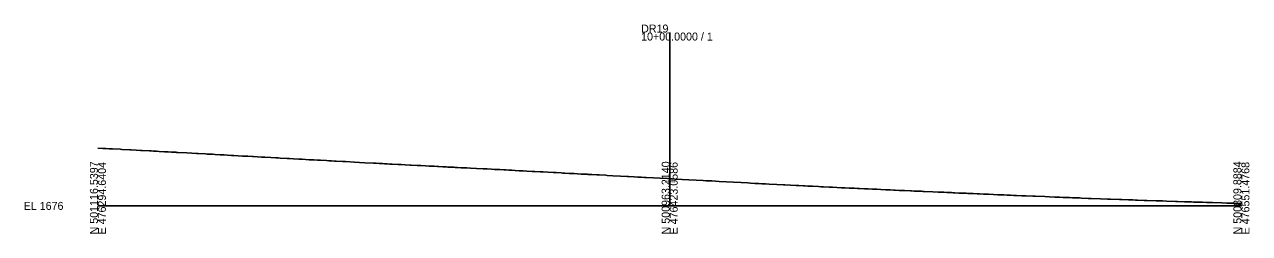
# Model space of a CAD drawing. Extents: x 79370 to 79799, y -95930 to -94349.
# Drawn here: x 79370.3 to 79798.8, y -95930.2 to -95856.9 of the extents above; entities that cross this region are included whole.
import ezdxf

# ---------------------------------------------------------------- set-up
doc = ezdxf.new("R2010")
doc.units = 0
for name, color, linetype in [('Exist Cross Section Cell', 7, 'Continuous'), ('Exist XS Center Line Elevation Label', 7, 'Continuous'), ('Exist XS Ground Line', 7, 'Continuous')]:
    doc.layers.add(name, color=color, linetype=linetype)

msp = doc.modelspace()

# ---------------------------------------------------------------- linework, layer by layer
at = {"layer": 'Exist Cross Section Cell'}
for p, q in [((79596.01, -95920.51), (79596.01, -95859.75)), ((79396.01, -95920.51), (79596.01, -95920.51)), ((79596.01, -95920.51), (79796.01, -95920.51))]:
    msp.add_line(p, q, dxfattribs=at)
at = {"layer": 'Exist XS Ground Line'}
msp.add_lwpolyline([(79396.01, -95900.26), (79397.73, -95900.35), (79398.72, -95900.4), (79399.88, -95900.47), (79400.53, -95900.5), (79401.09, -95900.53), (79403.77, -95900.68), (79404.31, -95900.71), (79407.19, -95900.86), (79407.62, -95900.88), (79409.4, -95900.98), (79410.89, -95901.06), (79411.53, -95901.09), (79414.03, -95901.23), (79414.67, -95901.26), (79415.41, -95901.3), (79416.52, -95901.36), (79417.44, -95901.41), (79419.3, -95901.52), (79420.55, -95901.59), (79421.79, -95901.66), (79423.27, -95901.73), (79423.64, -95901.76), (79423.95, -95901.77), (79427.09, -95901.94), (79428.91, -95902.04), (79430.47, -95902.13), (79431.04, -95902.16), (79433.6, -95902.3), (79434.19, -95902.33), (79434.9, -95902.37), (79436.03, -95902.43), (79436.99, -95902.49), (79438.8, -95902.58), (79440.11, -95902.66), (79441.31, -95902.73), (79442.7, -95902.8), (79443.15, -95902.83), (79443.53, -95902.85), (79446.63, -95903.02), (79448.43, -95903.12), (79450.05, -95903.21), (79450.46, -95903.23), (79453.18, -95903.38), (79453.73, -95903.41), (79454.34, -95903.45), (79456.52, -95903.57), (79458.25, -95903.66), (79459.05, -95903.71), (79459.76, -95903.75), (79462.18, -95903.88), (79462.98, -95903.92), (79464.36, -95904), (79466.34, -95904.11), (79467.42, -95904.17), (79469.91, -95904.31), (79471.51, -95904.39), (79472.87, -95904.46), (79473.81, -95904.52), (79476.01, -95904.63), (79476.81, -95904.68), (79477.71, -95904.73), (79478.74, -95904.79), (79479.33, -95904.82), (79481.64, -95904.94), (79482.08, -95904.97), (79482.61, -95905), (79485.76, -95905.17), (79487.46, -95905.26), (79489.4, -95905.36), (79492.35, -95905.52), (79492.8, -95905.54), (79493.31, -95905.57), (79494.39, -95905.63), (79495.58, -95905.69), (79496.29, -95905.72), (79497.22, -95905.77), (79498.17, -95905.83), (79498.95, -95905.87), (79501.04, -95905.98), (79501.38, -95906), (79502.09, -95906.04), (79503.46, -95906.11), (79505.27, -95906.2), (79505.57, -95906.21), (79507.68, -95906.33), (79508.93, -95906.39), (79510.55, -95906.47), (79511.86, -95906.55), (79512.25, -95906.57), (79512.73, -95906.59), (79513.66, -95906.63), (79514.82, -95906.69), (79515.23, -95906.72), (79516.63, -95906.79), (79517.77, -95906.84), (79518.45, -95906.88), (79519.47, -95906.93), (79520.56, -95906.99), (79520.96, -95907), (79521.76, -95907.04), (79523.02, -95907.11), (79524.54, -95907.18), (79525.08, -95907.21), (79526.28, -95907.27), (79528.4, -95907.38), (79530.74, -95907.5), (79531.44, -95907.54), (79531.76, -95907.55), (79532.17, -95907.57), (79533.67, -95907.65), (79534.77, -95907.71), (79536.12, -95907.78), (79536.64, -95907.8), (79537.96, -95907.87), (79538.72, -95907.92), (79539.79, -95907.97), (79540.85, -95908.02), (79541.99, -95908.09), (79543.37, -95908.16), (79544.05, -95908.2), (79544.81, -95908.24), (79546.1, -95908.31), (79547.88, -95908.4), (79548.86, -95908.45), (79550.69, -95908.55), (79551.1, -95908.57), (79551.75, -95908.61), (79553.44, -95908.7), (79555.27, -95908.8), (79556.35, -95908.86), (79558.07, -95908.95), (79558.64, -95908.99), (79559.29, -95909.02), (79560.85, -95909.1), (79561.29, -95909.13), (79562.57, -95909.2), (79563.76, -95909.26), (79565.06, -95909.33), (79566.07, -95909.39), (79567.15, -95909.44), (79567.5, -95909.46), (79568.73, -95909.53), (79570.57, -95909.63), (79571.4, -95909.67), (79573.7, -95909.79), (79574.12, -95909.81), (79576.16, -95909.92), (79578.85, -95910.06), (79581.15, -95910.19), (79581.63, -95910.21), (79583.55, -95910.32), (79584.85, -95910.39), (79585.21, -95910.41), (79586, -95910.45), (79587.26, -95910.52), (79587.75, -95910.55), (79590.3, -95910.68), (79592.68, -95910.81), (79595.22, -95910.95), (79596.01, -95910.99), (79597.77, -95911.09), (79600.36, -95911.22), (79602.68, -95911.35), (79605.3, -95911.49), (79607.67, -95911.61), (79608.8, -95911.67), (79610.16, -95911.75), (79610.78, -95911.78), (79613.37, -95911.92), (79615.84, -95912.06), (79618.36, -95912.2), (79621.05, -95912.34), (79623.36, -95912.47), (79624.23, -95912.51), (79625.84, -95912.6), (79627.25, -95912.67), (79628.27, -95912.73), (79629.52, -95912.79), (79630.86, -95912.86), (79633.52, -95913), (79635.86, -95913.12), (79636.3, -95913.14), (79638.32, -95913.24), (79640.27, -95913.34), (79640.73, -95913.36), (79641.14, -95913.38), (79642.87, -95913.47), (79643.34, -95913.49), (79644.35, -95913.54), (79645.64, -95913.61), (79646, -95913.63), (79648.12, -95913.73), (79649.03, -95913.78), (79649.81, -95913.81), (79651.78, -95913.91), (79652.24, -95913.93), (79652.58, -95913.95), (79652.93, -95913.97), (79654.49, -95914.04), (79656.17, -95914.12), (79657.37, -95914.18), (79658.84, -95914.25), (79659.61, -95914.29), (79660.52, -95914.33), (79661.68, -95914.38), (79662.37, -95914.42), (79664.15, -95914.5), (79664.82, -95914.53), (79665.41, -95914.56), (79666.99, -95914.63), (79668.5, -95914.7), (79669.86, -95914.77), (79671.67, -95914.85), (79672.4, -95914.88), (79673.11, -95914.91), (79674.47, -95914.98), (79674.94, -95915), (79676.3, -95915.06), (79677.45, -95915.11), (79678.21, -95915.15), (79680.21, -95915.23), (79680.65, -95915.25), (79681.49, -95915.29), (79684.12, -95915.4), (79684.59, -95915.43), (79685.01, -95915.44), (79688.08, -95915.58), (79689.93, -95915.67), (79691.6, -95915.73), (79691.92, -95915.75), (79693.01, -95915.81), (79694.6, -95915.87), (79695.14, -95915.89), (79695.8, -95915.92), (79697.12, -95915.99), (79697.85, -95916.02), (79698.68, -95916.05), (79699.68, -95916.1), (79700.34, -95916.13), (79701.11, -95916.16), (79702.22, -95916.21), (79703.56, -95916.27), (79704.35, -95916.3), (79705.76, -95916.36), (79707.57, -95916.44), (79709.31, -95916.52), (79710.81, -95916.58), (79711.33, -95916.6), (79712.87, -95916.67), (79714.05, -95916.71), (79715.24, -95916.76), (79716.43, -95916.82), (79717.32, -95916.85), (79719.16, -95916.93), (79720, -95916.97), (79720.62, -95916.99), (79723.01, -95917.09), (79723.99, -95917.13), (79727.27, -95917.26), (79728.79, -95917.32), (79730.8, -95917.4), (79732.34, -95917.46), (79733.68, -95917.52), (79734.17, -95917.54), (79734.69, -95917.56), (79735.89, -95917.6), (79736.88, -95917.64), (79738.56, -95917.71), (79739.41, -95917.74), (79740.11, -95917.77), (79742.46, -95917.86), (79743, -95917.88), (79743.42, -95917.9), (79746.71, -95918.02), (79749.16, -95918.11), (79750.28, -95918.15), (79753.34, -95918.26), (79753.72, -95918.28), (79754.18, -95918.29), (79756.53, -95918.38), (79757.23, -95918.41), (79758.06, -95918.44), (79758.97, -95918.47), (79759.72, -95918.49), (79761.96, -95918.57), (79762.47, -95918.59), (79762.89, -95918.6), (79766.22, -95918.72), (79768.46, -95918.79), (79769.79, -95918.84), (79772.93, -95918.94), (79773.25, -95918.95), (79773.63, -95918.97), (79776.11, -95919.05), (79776.74, -95919.07), (79777.53, -95919.09), (79778.5, -95919.12), (79779.27, -95919.15), (79781.42, -95919.21), (79781.98, -95919.23), (79782.43, -95919.25), (79783.83, -95919.29), (79785.93, -95919.35), (79789.22, -95919.45), (79790.95, -95919.5), (79792.35, -95919.54), (79793.1, -95919.57), (79794.42, -95919.61), (79795.48, -95919.64), (79796.01, -95919.65)], dxfattribs=at)

# ---------------------------------------------------------------- texts
at = {"layer": 'Exist Cross Section Cell'}
for s, p in [('DR19', (79586.01, -95859.75)), ('10+00.0000 / 1', (79586.01, -95862.55)), ('EL 1676', (79370.01, -95921.91))]:
    msp.add_text(s, height=2.8, dxfattribs=at).set_placement(p)
for s, p in [('N 501116.5397', (79396.01, -95930.51)), ('E 476294.6404', (79398.81, -95930.51)), ('N 500963.2140', (79596.01, -95930.51)), ('E 476423.0586', (79598.81, -95930.51)), ('N 500809.8884', (79796.01, -95930.51)), ('E 476551.4768', (79798.81, -95930.51))]:
    msp.add_text(s, height=2.8, rotation=90, dxfattribs=at).set_placement(p)
at = {"layer": 'Exist XS Center Line Elevation Label'}
msp.add_text('1685.52', height=0.75, dxfattribs=at).set_placement((79594.21, -95912.24))

doc.saveas('drawing.dxf')
